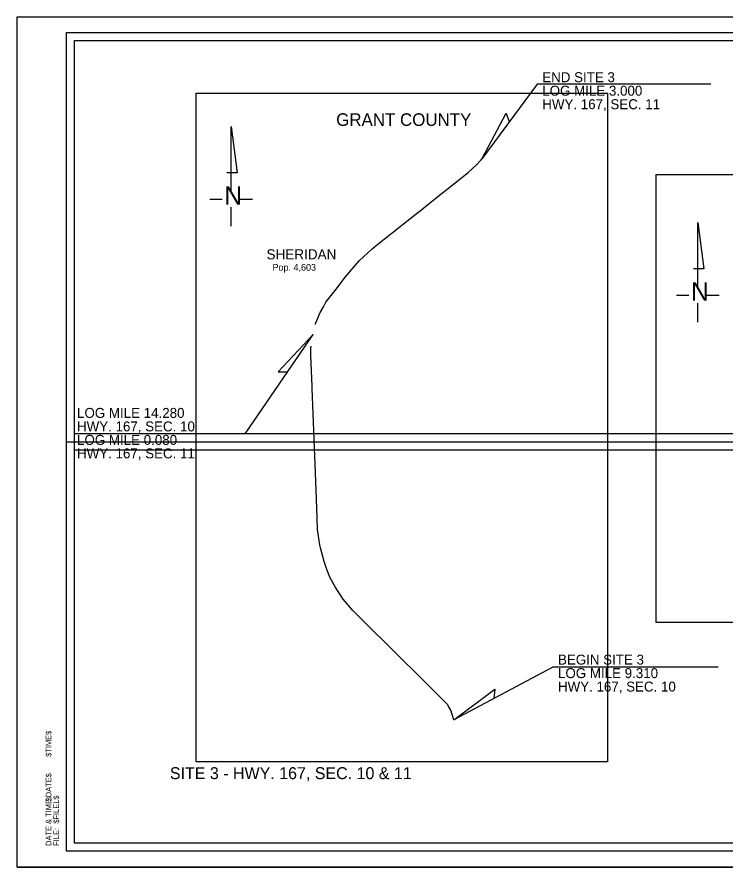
# Model space of a CAD drawing. Extents: x 10700 to 22009, y 10612 to 15552.
# Drawn here: x 14312 to 16090, y 13419 to 15552 of the extents above; entities that cross this region are included whole.
import ezdxf

# ---------------------------------------------------------------- set-up
doc = ezdxf.new("R2010")
doc.units = 0
for name, color, linetype in [('30', 7, 'Continuous'), ('Default', 7, 'Continuous'), ('Level 6', 7, 'Continuous'), ('R_Border', 7, 'Continuous'), ('R_Border Plan-Plan', 7, 'Continuous'), ('R_Dimension', 7, 'Continuous'), ('R_Draft', 7, 'Continuous'), ('R_No Plot', 7, 'Continuous')]:
    doc.layers.add(name, color=color, linetype=linetype)

msp = doc.modelspace()

# ---------------------------------------------------------------- linework, layer by layer
at = {"layer": 'Default'}
for points in [[(15061.1, 14780.7), (15062.2, 14784.6), (15072.5, 14810.1), (15080.9, 14824.9), (15087.2, 14836.2), (15093.7, 14844.7), (15109.9, 14866), (15136, 14900.3), (15170.5, 14939.8), (15202.7, 14969.8), (15217.7, 14981.7), (15233.6, 14994.4), (15317.2, 15061.1), (15323.2, 15065.9), (15355.6, 15091.7), (15410.9, 15135.8), (15443.6, 15162.1), (15464, 15180.2), (15476.3, 15193.4), (15479.4, 15198)], [(15408, 13788), (15400.3, 13812.1), (15395.7, 13820.5), (15391.7, 13826.3), (15382.8, 13836), (15332.4, 13885.8), (15181.8, 14035.1), (15154.5, 14062.2), (15130.1, 14091), (15110, 14121.6), (15096.9, 14146.2), (15089.1, 14165.5), (15082.6, 14185.8), (15073.8, 14219.9), (15071.9, 14227.5), (15066.2, 14265.4), (15064.9, 14294.6), (15062.9, 14365.5), (15052.6, 14619.6), (15052.3, 14625.6), (15049.6, 14702.5), (15049.6, 14719.8), (15050.4, 14725.7)]]:
    msp.add_lwpolyline(points, dxfattribs=at)
at = {"layer": 'R_Border'}
for p, q in [((14436.5, 15513.1), (17598.3, 15513.1)), ((14436.5, 13458.5), (14436.5, 15513.1)), ((15961.7, 15510.5), (15961.7, 15510.5)), ((15961.7, 15510.5), (15961.7, 15510.5)), ((14436.5, 13458.5), (14436.5, 13458.5)), ((17598.3, 13458.5), (14436.5, 13458.5))]:
    msp.add_line(p, q, dxfattribs=at)
at = {"layer": 'R_Border Plan-Plan'}
msp.add_line((14436.5, 14485.8), (17598.3, 14485.8), dxfattribs=at)
at = {"layer": 'R_Dimension'}
for p, q in [((16052.7, 15383.2), (15616.6, 15383.2)), ((14884.3, 14506.2), (14463, 14506.2)), ((16070.7, 13920.5), (15656.2, 13920.5))]:
    msp.add_line(p, q, dxfattribs=at)
for points in [[(15616.6, 15383.2), (15478.8, 15197.1), (15538.9, 15310.8), (15546.6, 15288.7)], [(14884.3, 14506.2), (15055.3, 14755), (14967.3, 14661.3), (14990.8, 14661.2)], [(15656.2, 13920.5), (15408, 13788), (15511, 13865), (15508.5, 13841.7)]]:
    msp.add_lwpolyline(points, dxfattribs=at)
at = {"layer": 'R_Draft'}
for p, q in [((14849.6, 15277), (14864.2, 15160.6)), ((14849.6, 15114.3), (14849.6, 15277)), ((14838.3, 15161.5), (14864.2, 15161.5)), ((14796.1, 15095.1), (14827, 15095.1)), ((14870.2, 15095.1), (14903.1, 15095.1)), ((14849.6, 15027), (14849.6, 15074.8)), ((16020.1, 15036.2), (16034.7, 14919.8)), ((16020.1, 14873.5), (16020.1, 15036.2)), ((16008.8, 14920.7), (16034.7, 14920.7)), ((15966.6, 14854.3), (15997.5, 14854.3)), ((16040.7, 14854.3), (16073.6, 14854.3)), ((16020.1, 14786.2), (16020.1, 14834.1))]:
    msp.add_line(p, q, dxfattribs=at)
at = {"layer": 'R_No Plot'}
for p, q in [((14312.5, 15552.1), (17645.8, 15552.1)), ((14312.5, 13418.7), (17645.8, 13418.7))]:
    msp.add_line(p, q, dxfattribs=at)
for points in [[(14312.4, 15552.1), (17645.8, 15552.1), (17645.8, 13418.7), (14312.4, 13418.7)], [(14456.5, 15493.1), (16951.9, 15493.1), (16951.9, 15394.3), (17127.3, 15394.3), (17368.3, 15394.3), (17368.3, 15171), (17578.3, 15171), (17578.3, 13478.5), (14456.5, 13478.5)], [(17578.3, 14505.8), (14456.5, 14505.8), (14456.5, 15493.1), (16951.9, 15493.1), (16951.9, 15394.3), (17127.3, 15394.3), (17368.3, 15394.3), (17368.3, 15171), (17578.3, 15171)], [(14761.6, 15360.8), (15793, 15360.8), (15793, 13682.8), (14761.6, 13682.8)], [(17460.7, 15156.8), (17460.7, 14032), (15915.5, 14032), (15915.5, 15156.8)], [(14456.5, 14465.8), (17578.3, 14465.8), (17578.3, 13478.5), (14456.5, 13478.5)]]:
    msp.add_lwpolyline(points, close=True, dxfattribs=at)

# ---------------------------------------------------------------- texts
at = {"layer": '30'}
msp.add_text('GRANT COUNTY', height=31.68, dxfattribs=at).set_placement((15112.9, 15278.7))
at = {"layer": 'Default'}
for s, height, p in [('$TIME$', 13.97, (14398.5, 13695.2)), ('$DATE$', 13.97, (14398.5, 13583.5)), ('DATE & TIME:', 13.968, (14398.5, 13471.8)), ('$FILEL$', 13.97, (14417.7, 13527.6)), ('FILE: ', 13.97, (14417.7, 13471.8))]:
    msp.add_text(s, height=height, rotation=90, dxfattribs=at).set_placement(p)
at = {"layer": 'Level 6'}
for s, height, p in [('SHERIDAN', 25.34, (14938.2, 14943.8)), ('Pop. 4,603', 16.9, (14953, 14915.2))]:
    msp.add_text(s, height=height, dxfattribs=at).set_placement(p)
at = {"layer": 'R_Dimension'}
for s, height, p in [('END SITE 3', 25, (15629.7, 15388.5)), ('LOG MILE 3.000', 25, (15629.7, 15354.6)), ('HWY. 167, SEC. 11', 25, (15629.7, 15320.7)), ('LOG MILE 14.280', 25, (14463, 14545.9)), ('HWY. 167, SEC. 10', 25, (14463, 14512)), ('LOG MILE 0.080', 25, (14463, 14478.2)), ('HWY. 167, SEC. 11', 25, (14463, 14444.3)), ('BEGIN SITE 3', 25, (15669.2, 13926.7)), ('LOG MILE 9.310', 25, (15669.2, 13892.8)), ('HWY. 167, SEC. 10', 25, (15669.2, 13859)), ('SITE 3 - HWY. 167, SEC. 10 & 11', 30, (14695.8, 13639.2))]:
    msp.add_text(s, height=height, rotation=359.9999, dxfattribs=at).set_placement(p)
at = {"layer": 'R_Draft'}
for p in [(14832, 15080.7), (16002.5, 14840)]:
    msp.add_text('N', height=46.5, dxfattribs=at).set_placement(p)

doc.saveas('drawing.dxf')
